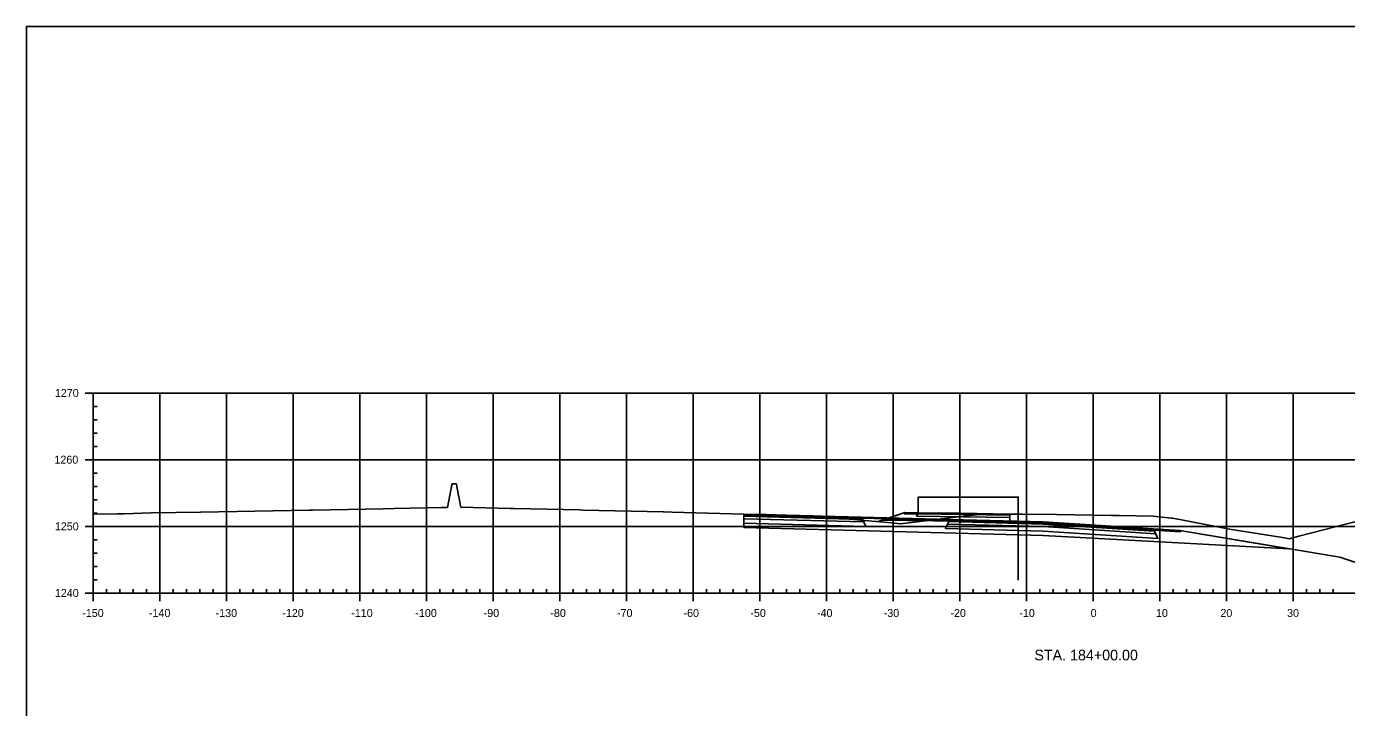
# Model space of a CAD drawing. Extents: x 659657 to 668193, y 633084 to 648639.
# Drawn here: x 667152.5 to 667350.5, y 643620.2 to 643722.4 of the extents above; entities that cross this region are included whole.
import ezdxf

# ---------------------------------------------------------------- set-up
doc = ezdxf.new("R2010")
doc.units = 0
for name, color, linetype in [('Default', 7, 'Continuous'), ('R_Axis', 7, 'Continuous'), ('R_Axis Annot', 7, 'Continuous'), ('R_Exist Surface', 7, 'Continuous'), ('R_Fin Surface', 7, 'Continuous'), ('R_Grid', 7, 'Continuous'), ('R_MOT_Stage 1B', 7, 'Continuous'), ('R_Sub Surface', 7, 'Continuous'), ('T_SIGNAL CONTROL CABINET', 7, 'Continuous'), ('TEMP_SIGNAL_HEAD_STAGE 5', 7, 'Continuous')]:
    doc.layers.add(name, color=color, linetype=linetype)

msp = doc.modelspace()

# ---------------------------------------------------------------- linework, layer by layer
for points in [[(667260.13, 643649.24), (667277.72, 643648.78), (667291.01, 643648.43), (667305, 643648.06), (667321.52, 643647), (667325.51, 643646.75), (667325.6, 643646.57), (667321.61, 643646.83), (667305, 643647.89), (667290.93, 643648.26), (667277.81, 643648.61), (667260.13, 643649.07)], [(667300.02, 643649.24), (667286.27, 643649.43), (667284.27, 643649.46), (667284.18, 643649.29), (667286.19, 643649.26), (667300.02, 643649.08)]]:
    msp.add_lwpolyline(points, close=True)
at = {"layer": 'Default'}
msp.add_lwpolyline([(667280.23, 643648.1), (667280.68, 643648.25), (667280.92, 643648.34), (667283, 643649.03), (667284.27, 643649.46), (667285.66, 643649.44), (667286.27, 643649.43), (667292.55, 643649.35), (667300.02, 643649.24)], dxfattribs=at)
at = {"layer": 'R_Axis'}
for p, q in [((667161.31, 643667.39), (667163.71, 643667.39)), ((667162.51, 643637.39), (667162.51, 643667.39)), ((667162.51, 643665.39), (667163.11, 643665.39)), ((667162.51, 643663.39), (667163.11, 643663.39)), ((667162.51, 643661.39), (667163.11, 643661.39)), ((667162.51, 643659.39), (667163.11, 643659.39)), ((667161.31, 643657.39), (667163.71, 643657.39)), ((667162.51, 643655.39), (667163.11, 643655.39)), ((667162.51, 643653.39), (667163.11, 643653.39)), ((667162.51, 643651.39), (667163.11, 643651.39)), ((667162.51, 643649.39), (667163.11, 643649.39)), ((667161.31, 643647.39), (667163.71, 643647.39)), ((667162.51, 643645.39), (667163.11, 643645.39)), ((667162.51, 643643.39), (667163.11, 643643.39)), ((667162.51, 643641.39), (667163.11, 643641.39)), ((667162.51, 643639.39), (667163.11, 643639.39)), ((667162.51, 643636.19), (667162.51, 643638.59)), ((667164.51, 643637.39), (667164.51, 643637.99)), ((667166.51, 643637.39), (667166.51, 643637.99)), ((667168.51, 643637.39), (667168.51, 643637.99)), ((667170.51, 643637.39), (667170.51, 643637.99)), ((667172.51, 643636.19), (667172.51, 643638.59)), ((667174.51, 643637.39), (667174.51, 643637.99)), ((667176.51, 643637.39), (667176.51, 643637.99)), ((667178.51, 643637.39), (667178.51, 643637.99)), ((667180.51, 643637.39), (667180.51, 643637.99)), ((667182.51, 643636.19), (667182.51, 643638.59)), ((667184.51, 643637.39), (667184.51, 643637.99)), ((667186.51, 643637.39), (667186.51, 643637.99)), ((667188.51, 643637.39), (667188.51, 643637.99)), ((667190.51, 643637.39), (667190.51, 643637.99)), ((667192.51, 643636.19), (667192.51, 643638.59)), ((667194.51, 643637.39), (667194.51, 643637.99)), ((667196.51, 643637.39), (667196.51, 643637.99)), ((667198.51, 643637.39), (667198.51, 643637.99)), ((667200.51, 643637.39), (667200.51, 643637.99)), ((667202.51, 643636.19), (667202.51, 643638.59)), ((667204.51, 643637.39), (667204.51, 643637.99)), ((667206.51, 643637.39), (667206.51, 643637.99)), ((667208.51, 643637.39), (667208.51, 643637.99)), ((667210.51, 643637.39), (667210.51, 643637.99)), ((667212.51, 643636.19), (667212.51, 643638.59)), ((667214.51, 643637.39), (667214.51, 643637.99)), ((667216.51, 643637.39), (667216.51, 643637.99)), ((667218.51, 643637.39), (667218.51, 643637.99)), ((667220.51, 643637.39), (667220.51, 643637.99)), ((667222.51, 643636.19), (667222.51, 643638.59)), ((667224.51, 643637.39), (667224.51, 643637.99)), ((667226.51, 643637.39), (667226.51, 643637.99)), ((667228.51, 643637.39), (667228.51, 643637.99)), ((667230.51, 643637.39), (667230.51, 643637.99)), ((667232.51, 643636.19), (667232.51, 643638.59)), ((667234.51, 643637.39), (667234.51, 643637.99)), ((667236.51, 643637.39), (667236.51, 643637.99)), ((667238.51, 643637.39), (667238.51, 643637.99)), ((667240.51, 643637.39), (667240.51, 643637.99)), ((667242.51, 643636.19), (667242.51, 643638.59)), ((667244.51, 643637.39), (667244.51, 643637.99)), ((667246.51, 643637.39), (667246.51, 643637.99)), ((667248.51, 643637.39), (667248.51, 643637.99)), ((667250.51, 643637.39), (667250.51, 643637.99)), ((667252.51, 643636.19), (667252.51, 643638.59)), ((667254.51, 643637.39), (667254.51, 643637.99)), ((667256.51, 643637.39), (667256.51, 643637.99)), ((667258.51, 643637.39), (667258.51, 643637.99)), ((667260.51, 643637.39), (667260.51, 643637.99)), ((667262.51, 643636.19), (667262.51, 643638.59)), ((667264.51, 643637.39), (667264.51, 643637.99)), ((667266.51, 643637.39), (667266.51, 643637.99)), ((667268.51, 643637.39), (667268.51, 643637.99)), ((667270.51, 643637.39), (667270.51, 643637.99)), ((667272.51, 643636.19), (667272.51, 643638.59)), ((667274.51, 643637.39), (667274.51, 643637.99)), ((667276.51, 643637.39), (667276.51, 643637.99)), ((667278.51, 643637.39), (667278.51, 643637.99)), ((667280.51, 643637.39), (667280.51, 643637.99)), ((667282.51, 643636.19), (667282.51, 643638.59)), ((667284.51, 643637.39), (667284.51, 643637.99)), ((667286.51, 643637.39), (667286.51, 643637.99)), ((667288.51, 643637.39), (667288.51, 643637.99)), ((667290.51, 643637.39), (667290.51, 643637.99)), ((667292.51, 643636.19), (667292.51, 643638.59)), ((667294.51, 643637.39), (667294.51, 643637.99)), ((667296.51, 643637.39), (667296.51, 643637.99)), ((667298.51, 643637.39), (667298.51, 643637.99)), ((667300.51, 643637.39), (667300.51, 643637.99)), ((667302.51, 643636.19), (667302.51, 643638.59)), ((667304.51, 643637.39), (667304.51, 643637.99)), ((667306.51, 643637.39), (667306.51, 643637.99)), ((667308.51, 643637.39), (667308.51, 643637.99)), ((667310.51, 643637.39), (667310.51, 643637.99)), ((667312.51, 643636.19), (667312.51, 643638.59)), ((667314.51, 643637.39), (667314.51, 643637.99)), ((667316.51, 643637.39), (667316.51, 643637.99)), ((667318.51, 643637.39), (667318.51, 643637.99)), ((667320.51, 643637.39), (667320.51, 643637.99)), ((667322.51, 643636.19), (667322.51, 643638.59)), ((667324.51, 643637.39), (667324.51, 643637.99)), ((667326.51, 643637.39), (667326.51, 643637.99)), ((667328.51, 643637.39), (667328.51, 643637.99)), ((667330.51, 643637.39), (667330.51, 643637.99)), ((667332.51, 643636.19), (667332.51, 643638.59)), ((667334.51, 643637.39), (667334.51, 643637.99)), ((667336.51, 643637.39), (667336.51, 643637.99)), ((667338.51, 643637.39), (667338.51, 643637.99)), ((667340.51, 643637.39), (667340.51, 643637.99)), ((667342.51, 643636.19), (667342.51, 643638.59)), ((667344.51, 643637.39), (667344.51, 643637.99)), ((667346.51, 643637.39), (667346.51, 643637.99)), ((667348.51, 643637.39), (667348.51, 643637.99)), ((667161.31, 643637.39), (667163.71, 643637.39)), ((667162.51, 643637.39), (667462.51, 643637.39))]:
    msp.add_line(p, q, dxfattribs=at)
at = {"layer": 'R_Exist Surface'}
msp.add_lwpolyline([(667162.51, 643649.23), (667166.2, 643649.25), (667167.19, 643649.25), (667171.16, 643649.42), (667178.62, 643649.54), (667194.92, 643649.83), (667195.34, 643649.84), (667195.42, 643649.84), (667205.97, 643650.04), (667207.67, 643650.07), (667214.78, 643650.21), (667215.67, 643650.22), (667216.27, 643653.35), (667216.34, 643653.72), (667216.34, 643653.72), (667216.34, 643653.76), (667216.41, 643653.76), (667217.01, 643653.76), (667217.01, 643653.76), (667217.01, 643653.76), (667217.08, 643653.39), (667217.68, 643650.26), (667225.04, 643650.09), (667225.68, 643650.07), (667235.5, 643649.85), (667236, 643649.84), (667248.03, 643649.56), (667248.15, 643649.56), (667249.36, 643649.53), (667260.07, 643649.24), (667263.53, 643649.15), (667266.48, 643649.07), (667270.54, 643648.97), (667273.53, 643648.69), (667273.97, 643648.65), (667274.13, 643648.64), (667282.23, 643647.93), (667283.59, 643647.76), (667283.59, 643647.76), (667283.61, 643647.77), (667293.93, 643649), (667295.02, 643649.12), (667296.43, 643649.29), (667297.51, 643649.28), (667300.02, 643649.24), (667301.13, 643649.24), (667301.92, 643649.23), (667306.98, 643649.15), (667309.7, 643649.11), (667315.25, 643649.04), (667316.42, 643649.02), (667321.5, 643648.93), (667324.18, 643648.64), (667324.39, 643648.61), (667325.73, 643648.36), (667332.94, 643646.99), (667340.89, 643645.7), (667341.89, 643645.53), (667343.35, 643645.91), (667352.7, 643648.34)], dxfattribs=at)
at = {"layer": 'R_Fin Surface'}
for points in [[(667260.13, 643649.07), (667277.81, 643648.61), (667277.89, 643648.44), (667260.13, 643648.91)], [(667260.13, 643648.91), (667277.89, 643648.44), (667278.08, 643648.06), (667260.13, 643648.53)], [(667260.13, 643648.53), (667278.08, 643648.06), (667278.42, 643647.38), (667260.13, 643647.87)], [(667300.02, 643649.08), (667286.19, 643649.26), (667286.02, 643648.93), (667300.02, 643648.74)], [(667290.85, 643648.1), (667305, 643647.72), (667321.69, 643646.66), (667321.88, 643646.27), (667305, 643647.35), (667290.66, 643647.73)], [(667321.61, 643646.83), (667305, 643647.89), (667290.93, 643648.26), (667290.85, 643648.1), (667305, 643647.72), (667321.69, 643646.66)], [(667290.66, 643647.73), (667305, 643647.35), (667321.88, 643646.27), (667322.22, 643645.59), (667305, 643646.68), (667290.34, 643647.08)]]:
    msp.add_lwpolyline(points, close=True, dxfattribs=at)
at = {"layer": 'R_Grid'}
for p, q in [((667162.51, 643667.39), (667462.51, 643667.39)), ((667162.51, 643637.39), (667162.51, 643667.39)), ((667172.51, 643637.39), (667172.51, 643667.39)), ((667182.51, 643637.39), (667182.51, 643667.39)), ((667192.51, 643637.39), (667192.51, 643667.39)), ((667202.51, 643637.39), (667202.51, 643667.39)), ((667212.51, 643637.39), (667212.51, 643667.39)), ((667222.51, 643637.39), (667222.51, 643667.39)), ((667232.51, 643637.39), (667232.51, 643667.39)), ((667242.51, 643637.39), (667242.51, 643667.39)), ((667252.51, 643637.39), (667252.51, 643667.39)), ((667262.51, 643637.39), (667262.51, 643667.39)), ((667272.51, 643637.39), (667272.51, 643667.39)), ((667282.51, 643637.39), (667282.51, 643667.39)), ((667292.51, 643637.39), (667292.51, 643667.39)), ((667302.51, 643637.39), (667302.51, 643667.39)), ((667312.51, 643637.39), (667312.51, 643667.39)), ((667322.51, 643637.39), (667322.51, 643667.39)), ((667332.51, 643637.39), (667332.51, 643667.39)), ((667342.51, 643637.39), (667342.51, 643667.39)), ((667162.51, 643657.39), (667462.51, 643657.39)), ((667162.51, 643647.39), (667462.51, 643647.39)), ((667162.51, 643637.39), (667462.51, 643637.39))]:
    msp.add_line(p, q, dxfattribs=at)
at = {"layer": 'R_MOT_Stage 1B'}
msp.add_lwpolyline([(667286.27, 643649.43), (667286.27, 643651.78), (667301.27, 643651.78), (667301.27, 643639.3)], dxfattribs=at)
at = {"layer": 'R_Sub Surface'}
for points in [[(667260.13, 643647.87), (667278.42, 643647.38), (667277.81, 643648.61), (667290.93, 643648.26), (667290.34, 643647.08), (667305, 643646.68), (667322.22, 643645.59), (667321.61, 643646.83), (667325.6, 643646.57), (667325.51, 643646.75), (667341.85, 643644.02), (667305, 643646.01), (667260.13, 643647.2)], [(667300.02, 643648.74), (667286.02, 643648.93), (667286.19, 643649.26), (667300.02, 643649.08), (667286.19, 643649.26), (667284.18, 643649.29), (667284.27, 643649.46), (667280.92, 643648.34), (667300.02, 643648.08)]]:
    msp.add_lwpolyline(points, close=True, dxfattribs=at)
at = {"layer": 'T_SIGNAL CONTROL CABINET'}
msp.add_lwpolyline([(667152.51, 643502.39), (667492.51, 643502.39), (667492.51, 643722.39), (667152.51, 643722.39)], close=True, dxfattribs=at)
at = {"layer": 'TEMP_SIGNAL_HEAD_STAGE 5'}
for points in [[(667325.51, 643646.75), (667349.47, 643642.75), (667356.95, 643640.25), (667387.63, 643650.48)], [(667284.27, 643649.46), (667280.23, 643648.1)]]:
    msp.add_lwpolyline(points, dxfattribs=at)

# ---------------------------------------------------------------- texts
at = {"layer": 'R_Axis Annot'}
for s, height, p in [('1270', 1.2, (667156.78, 643666.79)), ('1260', 1.2, (667156.72, 643656.79)), ('1250', 1.2, (667156.78, 643646.79)), ('1240', 1.2, (667156.78, 643636.79)), ('-150', 1.2, (667160.89, 643633.79)), ('-140', 1.2, (667170.89, 643633.79)), ('-130', 1.2, (667180.89, 643633.79)), ('-120', 1.2, (667190.89, 643633.79)), ('-110', 1.2, (667201.23, 643633.79)), ('-100', 1.2, (667210.84, 643633.79)), ('-90', 1.2, (667221.09, 643633.79)), ('-80', 1.2, (667231.09, 643633.79)), ('-70', 1.2, (667241.09, 643633.79)), ('-60', 1.2, (667251.06, 643633.79)), ('-50', 1.2, (667261.09, 643633.79)), ('-40', 1.2, (667271.09, 643633.79)), ('-30', 1.2, (667281.09, 643633.79)), ('-20', 1.2, (667291.09, 643633.79)), ('-10', 1.2, (667301.43, 643633.79)), ('0', 1.2, (667312.12, 643633.79)), ('10', 1.2, (667321.92, 643633.79)), ('20', 1.2, (667331.58, 643633.79)), ('30', 1.2, (667341.58, 643633.79)), ('STA. 184+00.00', 1.6, (667303.68, 643627.29))]:
    msp.add_text(s, height=height, dxfattribs=at).set_placement(p)

doc.saveas('drawing.dxf')
